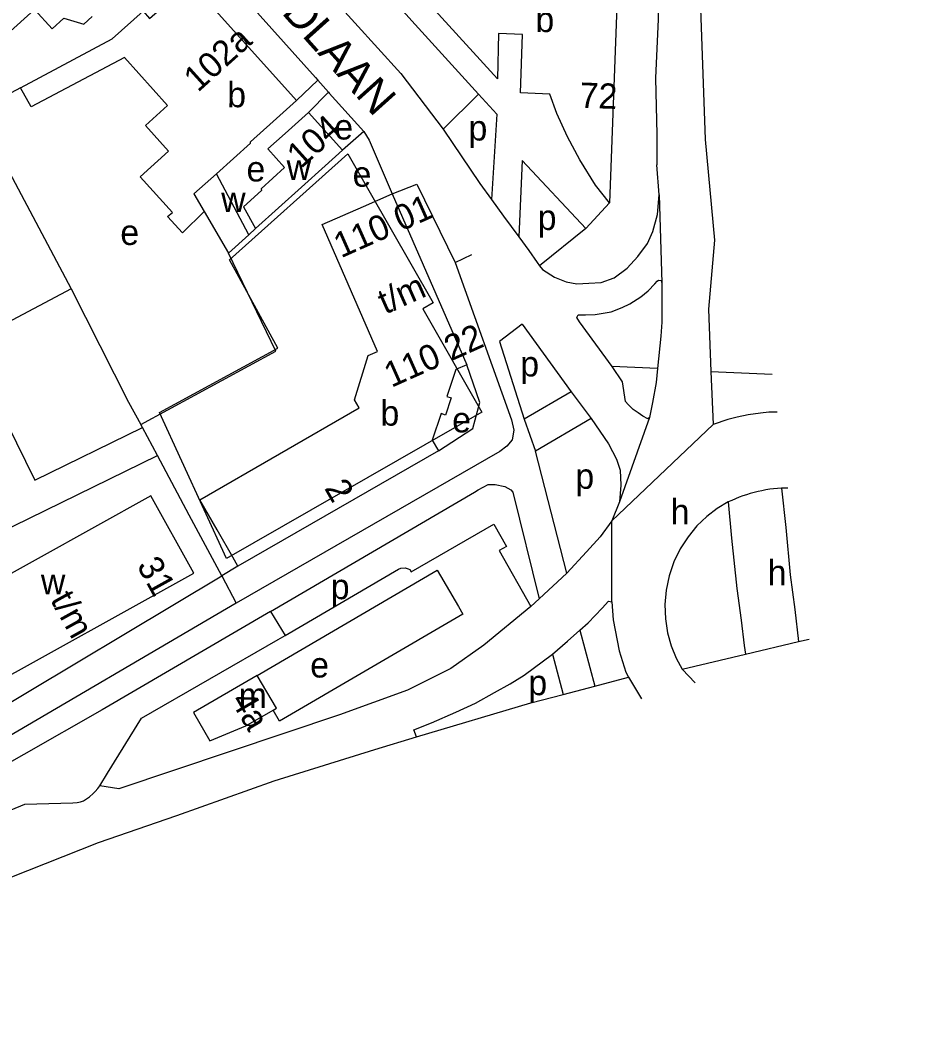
# Model space of a CAD drawing. Extents: x 158356 to 159894, y 383831 to 385260.
# Drawn here: x 159143.9 to 159285.1, y 383926.7 to 384085.1 of the extents above; entities that cross this region are included whole.
import ezdxf

# ---------------------------------------------------------------- set-up
doc = ezdxf.new("R2010")
doc.units = 0
for name, color, linetype in [('BLT_Basislijn', 7, 'Continuous'), ('BLT_Bebouwing', 7, 'Continuous'), ('BLT_Centroide', 7, 'Continuous'), ('BLT_Huisnummer', 7, 'Continuous'), ('BLT_Huisnummer_reeks', 7, 'Continuous'), ('BLT_Onderverdeling_panden', 7, 'Continuous'), ('BLT_Plantopo', 7, 'Continuous'), ('BLT_Straatnaam', 7, 'Continuous'), ('BLT_Vlakafsluiter', 7, 'Continuous')]:
    doc.layers.add(name, color=color, linetype=linetype)

msp = doc.modelspace()

# ---------------------------------------------------------------- linework, layer by layer
at = {"layer": 'BLT_Basislijn'}
for p, q in [((159199.69, 384091.99), (159206.51, 384084.38)), ((159192.14, 384089.95), (159204.25, 384076.61)), ((159216.57, 384073.35), (159206.51, 384084.38)), ((159204.25, 384076.61), (159210.95, 384067.81)), ((159187.7, 384072.36), (159191.11, 384075.54)), ((159191.11, 384075.54), (159192.79, 384073.64)), ((159189.62, 384070.45), (159192.79, 384073.64)), ((159216.57, 384073.35), (159210.95, 384067.81)), ((159216.57, 384073.35), (159219.47, 384070.16)), ((159219.47, 384070.16), (159218.6, 384056.68)), ((159198.4, 384067.44), (159195.01, 384064.47)), ((159223.46, 384062.84), (159222.93, 384050.73)), ((159223.46, 384062.84), (159233.57, 384052.05)), ((159181.22, 384052.05), (159180.14, 384051.05)), ((159233.57, 384052.05), (159226.21, 384046.16)), ((159223.46, 384036.93), (159219.88, 384034.18)), ((159219.88, 384034.18), (159223.81, 384021.85)), ((159244.93, 384029.9), (159237.71, 384030.19)), ((159253.37, 384029.43), (159263.07, 384028.97)), ((159231.24, 384026.17), (159223.81, 384021.85)), ((159231.24, 384026.17), (159234.38, 384021.97)), ((159163.28, 384020.54), (159163.03, 384021.01)), ((159223.81, 384021.85), (159225.6, 384016.76)), ((159234.38, 384021.97), (159225.6, 384016.76)), ((159165.67, 384016.08), (159163.28, 384020.54)), ((159122.87, 383995.19), (159165.67, 384016.08)), ((159230.54, 383997.45), (159225.6, 384016.76)), ((159178.42, 383998.58), (159175.88, 383997.05)), ((159175.88, 383997.05), (159178.17, 383992.69)), ((159181.48, 383981.26), (159209.99, 383997.95)), ((159209.99, 383997.95), (159213.37, 383992.16)), ((159183.57, 383991.39), (159185.91, 383987.57)), ((159214.05, 383990.98), (159185.03, 383974.01)), ((159213.37, 383992.16), (159214.05, 383990.98)), ((159232.63, 383988.41), (159234.96, 383979.56)), ((159258.87, 383984.61), (159267.28, 383986.61)), ((159267.28, 383986.61), (159268.97, 383987.01)), ((159228.29, 383984.6), (159229.96, 383978.25)), ((159248.82, 383982.23), (159258.87, 383984.61)), ((159185.03, 383974.01), (159184.01, 383975.77))]:
    msp.add_line(p, q, dxfattribs=at)
for points in [[(159281.76, 384205.96), (159281.76, 384205.96), (159276.27, 384198.65), (159273.07, 384193.62), (159268.51, 384186.31), (159265.31, 384179.22), (159262.11, 384172.13), (159258.23, 384163.68), (159256.66, 384157.61), (159252.55, 384146.41), (159250.26, 384136.36), (159249.12, 384127.9), (159248.21, 384122.19), (159245.24, 384093.84), (159245.03, 384085.25), (159244.57, 384075.88), (159244.8, 384066.97), (159244.8, 384062.17)], [(159285.08, 384202.55), (159279.24, 384194.76), (159277.53, 384191.59), (159273.88, 384185.74), (159268.77, 384176.24), (159264.87, 384166.99), (159261.47, 384157.49), (159258.06, 384147.25), (159255.87, 384137.51), (159253.92, 384128.74), (159252.46, 384119.48), (159251.97, 384109.01), (159251.48, 384094.39), (159252.46, 384066.14), (159253.94, 384050.22), (159252.97, 384039.26), (159253.37, 384029.43)], [(159150.1, 384121.32), (159190.71, 384075.98), (159191.11, 384075.54)], [(159192.79, 384073.64), (159192.9, 384073.52), (159198.4, 384067.44)], [(159198.4, 384067.44), (159199.22, 384066.08), (159202.88, 384057.53)], [(159210.95, 384067.81), (159216.77, 384059.21), (159218.6, 384056.68)], [(159245.15, 384057.4), (159244.8, 384062.17)], [(159130.07, 384059.7), (159124.27, 384056.8), (159146.23, 384012.21), (159163.28, 384020.54)], [(159202.88, 384057.53), (159206.77, 384059.06), (159212.87, 384046.65)], [(159226.21, 384046.16), (159226.67, 384045.56), (159228.61, 384044.36), (159230.42, 384043.63), (159232.11, 384043.27), (159234.04, 384043.39), (159235.97, 384043.51), (159238.02, 384044.23), (159240.08, 384045.8), (159241.77, 384047.62), (159243.34, 384049.67), (159244.18, 384051.6), (159244.91, 384054.26), (159245.15, 384057.4)], [(159218.6, 384056.68), (159220.52, 384054.02), (159222.93, 384050.73)], [(159237.3, 384056.11), (159233.57, 384052.05)], [(159222.93, 384050.73), (159224.5, 384048.58), (159225.83, 384046.65), (159226.21, 384046.16)], [(159163.03, 384021.01), (159184.45, 384032.63), (159176.91, 384048.14)], [(159212.87, 384046.65), (159215.48, 384047.95)], [(159212.87, 384046.65), (159221.79, 384021.74), (159222.12, 384020.1), (159221.9, 384018.58), (159221.03, 384017.6), (159219.94, 384016.73), (159178.17, 383992.69)], [(159232.12, 384037.94), (159232.32, 384038.39), (159233.51, 384038.39), (159235.02, 384038.44), (159237.58, 384038.86), (159239.29, 384039.53), (159240.53, 384040.1), (159242.28, 384041.24), (159243.42, 384042.19), (159244.51, 384043.28), (159244.84, 384043.7), (159245.08, 384043.89), (159245.51, 384043.8), (159245.6, 384043.47)], [(159245.6, 384043.47), (159245.6, 384040.29), (159245.6, 384037.2), (159245.46, 384035.02), (159244.93, 384029.9)], [(159152.02, 384042.49), (159161.11, 384024.56), (159163.03, 384021.01)], [(159223.46, 384036.93), (159231.24, 384026.17)], [(159237.71, 384030.19), (159232.56, 384037.25), (159232.12, 384037.94)], [(159210.19, 384016.86), (159215.67, 384020.37), (159216.74, 384024.48), (159214.68, 384030.46)], [(159243.66, 384022.11), (159243.37, 384021.92), (159242.61, 384022.35), (159241.85, 384022.87), (159241.05, 384023.39), (159240.29, 384024.15), (159239.86, 384024.63), (159239.39, 384027.76), (159237.71, 384030.19)], [(159244.93, 384029.9), (159244.7, 384027.66), (159244.13, 384024.49), (159243.66, 384022.11)], [(159253.37, 384029.43), (159253.72, 384021.01)], [(159263.87, 384022.98), (159262.54, 384022.95), (159261.24, 384022.8), (159259.27, 384022.54), (159257.56, 384022.16), (159256.05, 384021.8), (159253.72, 384021.01)], [(159263.87, 384022.98), (159263.87, 384022.98)], [(159234.38, 384021.97), (159237.14, 384017.92), (159238.44, 384015.53), (159238.99, 384013.79), (159239.1, 384011.39), (159238.88, 384008.78)], [(159175.88, 383997.05), (159170.71, 384006.63), (159165.67, 384016.08)], [(159216.49, 384010.65), (159218.09, 384011.5), (159219.18, 384011.5), (159220.7, 384011.17), (159221.68, 384010.63), (159222.01, 384010.3), (159226.18, 383993.41)], [(159183.57, 383991.39), (159215.91, 384010.3), (159216.49, 384010.65)], [(159264.55, 384010.93), (159263.93, 384010.89), (159263.31, 384010.82), (159262.69, 384010.74), (159262.07, 384010.64), (159261.45, 384010.52), (159260.84, 384010.39), (159260.23, 384010.24), (159259.62, 384010.07), (159259.02, 384009.89), (159258.42, 384009.69), (159257.83, 384009.47), (159257.25, 384009.24), (159256.68, 384008.99), (159256.11, 384008.73)], [(159265.58, 384010.91), (159265.23, 384010.93), (159264.55, 384010.93)], [(159264.55, 384010.93), (159265.24, 384004.67), (159265.95, 383997.17), (159266.67, 383991.72), (159267.28, 383986.61)], [(159238.88, 384008.78), (159237.68, 384005.73)], [(159256.11, 384008.73), (159254.39, 384007.69), (159252.73, 384006.43), (159251.17, 384004.94), (159249.75, 384003.23), (159248.52, 384001.32), (159247.51, 383999.25), (159246.75, 383997.05), (159246.28, 383994.77), (159246.08, 383992.48), (159246.16, 383990.21), (159246.51, 383988.01), (159247.09, 383985.93), (159247.87, 383983.99), (159248.82, 383982.23)], [(159256.11, 384008.73), (159256.66, 384002.98), (159257.47, 383995.02), (159258.18, 383990.02), (159258.63, 383986), (159258.87, 383984.61)], [(159203.88, 383998.11), (159204.25, 383998.23), (159204.91, 383998.31), (159205.42, 383998.14), (159205.67, 383998.06), (159205.89, 383997.68), (159219, 384005.2), (159220.96, 384001.68), (159219.82, 384001.04), (159224.83, 383992.17)], [(159237.68, 384005.73), (159235.83, 384003.22), (159233.65, 384000.83), (159230.54, 383997.45)], [(159132.98, 383974.65), (159137.54, 383974.11), (159175.88, 383997.05)], [(159185.91, 383987.57), (159203.88, 383998.11)], [(159230.54, 383997.45), (159226.18, 383993.41)], [(159178.17, 383992.69), (159137.39, 383968.84), (159136.17, 383968.1)], [(159224.83, 383992.17), (159226.18, 383993.41)], [(159232.63, 383988.41), (159233.95, 383989.59), (159236.17, 383991.89), (159237.17, 383993.03), (159237.67, 383992.89)], [(159237.67, 383992.89), (159237.91, 383990.08), (159238.82, 383985.15), (159239.89, 383981.78), (159240.3, 383980.96)], [(159183.57, 383991.39), (159156.91, 383975.82), (159119.63, 383954.56), (159067.69, 383929.66)], [(159224.83, 383992.17), (159217.41, 383986.05), (159212.15, 383982.36), (159205.31, 383978.94), (159194.53, 383975), (159159.57, 383963.29), (159156.54, 383963.75)], [(159156.54, 383963.75), (159157.76, 383965.78), (159163.15, 383974.46), (159184.81, 383986.93), (159185.91, 383987.57)], [(159228.29, 383984.6), (159230.66, 383986.66), (159232.63, 383988.41)], [(159206.72, 383971.51), (159206.31, 383972.61), (159209.11, 383973.76), (159212.97, 383975.41), (159216.05, 383976.84), (159219.06, 383978.56), (159221.56, 383979.92), (159223.78, 383981.28), (159228.29, 383984.6)], [(159234.96, 383979.56), (159240.3, 383980.96)], [(159206.72, 383971.51), (159224.84, 383976.91), (159229.96, 383978.25)], [(159229.96, 383978.25), (159234.96, 383979.56)], [(159088.93, 383926.66), (159102.6, 383932.65), (159121.62, 383940.74), (159139.46, 383948.12), (159156.35, 383954.78), (159168.72, 383959.06), (159184.17, 383964.54), (159200.11, 383969.53), (159206.72, 383971.51)], [(159152.29, 383961.04), (159152.96, 383961.1), (159153.49, 383961.21), (159153.95, 383961.37), (159154.44, 383961.69), (159154.88, 383962.04), (159155.51, 383962.54), (159155.82, 383962.86), (159156.25, 383963.33), (159156.54, 383963.75)], [(159081.85, 383931.35), (159109.84, 383943.2), (159117.99, 383946.75), (159125.88, 383953.07), (159144.67, 383960.83), (159152.29, 383961.04)]]:
    msp.add_lwpolyline(points, dxfattribs=at)
at = {"layer": 'BLT_Bebouwing'}
for p, q in [((159170.89, 384091.03), (159187.7, 384072.36)), ((159143.99, 384074.36), (159139.58, 384072.02)), ((159195.01, 384064.47), (159189.62, 384070.45)), ((159140.09, 384064.94), (159152.02, 384042.49)), ((159180.14, 384051.05), (159175.03, 384060.7)), ((159202.88, 384057.53), (159214.68, 384030.46)), ((159173.08, 384054.74), (159176.91, 384048.14)), ((159176.91, 384048.14), (159180.14, 384051.05)), ((159181.48, 383981.26), (159171.39, 383975.38))]:
    msp.add_line(p, q, dxfattribs=at)
for points in [[(159239.94, 384109.7), (159239.35, 384092.98), (159238.7, 384093), (159237.3, 384056.11)], [(159227.86, 384073.32), (159223.22, 384073.57), (159223.51, 384082.82), (159219.74, 384082.98), (159219.55, 384075.78), (159199.19, 384098.16)], [(159135.19, 384076.87), (159146.19, 384086.78), (159149, 384083.71), (159150.86, 384085.39), (159154.01, 384084.46), (159155.32, 384085.64)], [(159168.04, 384054.62), (159162.95, 384060.27), (159167.43, 384064.31), (159163.76, 384068.38), (159167.29, 384071.56), (159160.47, 384079.13), (159145.64, 384071.35), (159143.99, 384074.36)], [(159237.3, 384056.11), (159235.08, 384058.94), (159232.6, 384062.92), (159230.65, 384066.6), (159228.98, 384070.29), (159227.86, 384073.32)], [(159175.03, 384060.7), (159180.44, 384065.57), (159180.4, 384065.78), (159183.99, 384069.01), (159187.7, 384072.36)], [(159189.62, 384070.45), (159185.9, 384067.11), (159183.18, 384064.66), (159185.83, 384061.72), (159182.11, 384058.37), (159182.17, 384058.09), (159179.32, 384055.52), (159181.22, 384052.05)], [(159181.22, 384052.05), (159188.49, 384058.61), (159192.27, 384062)], [(159152.02, 384042.49), (159140.94, 384036.66), (159137.71, 384042.74), (159140.84, 384044.23), (159137.16, 384051.97), (159134.68, 384050.7), (159130.07, 384059.7)], [(159178.42, 383998.58), (159177.6, 384000), (159175.11, 384004.33), (159172.37, 384009.09), (159197.63, 384023.63), (159196.91, 384024.89), (159199.09, 384031.94), (159200.52, 384032.57), (159191.75, 384052.67), (159198.3, 384055.53), (159202.88, 384057.53)], [(159173.08, 384054.74), (159169.62, 384051.35), (159167.28, 384053.94), (159168.04, 384054.62)], [(159214.68, 384030.46), (159212.94, 384029.7), (159211.52, 384025.45), (159212.21, 384025.22), (159211.3, 384022.5), (159210.62, 384022.73), (159209.22, 384018.54), (159210.19, 384016.86)], [(159210.19, 384016.86), (159180.9, 384000), (159178.42, 383998.58)], [(159137.34, 383978.53), (159171.42, 383997.44), (159164.61, 384009.71), (159137.81, 383994.83), (159136.03, 383998.02), (159128.76, 383993.98), (159137.34, 383978.53)], [(159184.01, 383975.77), (159184.52, 383976.06), (159181.48, 383981.26)], [(159171.39, 383975.38), (159173.99, 383970.91), (159179.67, 383973.24), (159184.01, 383975.77)]]:
    msp.add_lwpolyline(points, dxfattribs=at)
at = {"layer": 'BLT_Onderverdeling_panden'}
for p, q in [((159143.99, 384074.36), (159158.52, 384082.1)), ((159195.01, 384064.47), (159192.27, 384062)), ((159175.03, 384060.7), (159171.43, 384057.57)), ((159171.43, 384057.57), (159173.08, 384054.74))]:
    msp.add_line(p, q, dxfattribs=at)
msp.add_lwpolyline([(159158.52, 384082.1), (159163.43, 384086.47), (159164.43, 384085.34), (159170.89, 384091.03)], dxfattribs=at)
at = {"layer": 'BLT_Plantopo'}
msp.add_lwpolyline([(159166, 384022.9), (159184.75, 384033.09), (159177.11, 384047.12), (159195.82, 384063.88), (159209.36, 384040.28), (159207.71, 384039.33), (159217.06, 384022.97), (159176.6, 383999.8)], close=True, dxfattribs=at)
at = {"layer": 'BLT_Vlakafsluiter'}
for p, q in [((159245.15, 384057.4), (159245.6, 384043.47)), ((159237.68, 384005.73), (159253.72, 384021.01)), ((159243.66, 384022.11), (159238.88, 384008.78)), ((159237.67, 383992.89), (159237.68, 384005.73)), ((159248.82, 383982.23), (159250.87, 383980.07)), ((159240.3, 383980.96), (159242.37, 383977.54))]:
    msp.add_line(p, q, dxfattribs=at)

# ---------------------------------------------------------------- texts
at = {"layer": 'BLT_Centroide'}
for s, p in [('b', (159225.57, 384083.19)), ('b', (159176.73, 384071.28)), ('e', (159193.7, 384066.16)), ('p', (159214.97, 384066)), ('e', (159179.79, 384059.51)), ('w', (159186.15, 384059.77)), ('e', (159196.6, 384058.68)), ('w', (159175.78, 384054.67)), ('p', (159225.93, 384051.83)), ('e', (159159.79, 384049.45)), ('p', (159223.17, 384028.62)), ('b', (159201.02, 384020.83)), ('e', (159212.38, 384019.76)), ('p', (159231.9, 384010.82)), ('h', (159247, 384005.19)), ('h', (159262.37, 383995.54)), ('w', (159147.21, 383994.12)), ('p', (159193.14, 383993.33)), ('e', (159189.88, 383980.92)), ('p', (159224.45, 383978.12)), ('m', (159178.55, 383976.09))]:
    msp.add_text(s, height=4, dxfattribs=at).set_placement(p)
at = {"layer": 'BLT_Huisnummer'}
for s, rotation, p in [('102a', 42.0279, (159172.08, 384073.54)), ('104', 42.0065, (159188.43, 384061.46)), ('110 01', 24.0065, (159194.75, 384047.32)), ('t/m', 24.0065, (159201.76, 384038.4)), ('110 22', 24.0065, (159202.74, 384026.8)), ('4a', 300.2437, (159177.18, 383977.29))]:
    msp.add_text(s, height=4, rotation=rotation, dxfattribs=at).set_placement(p)
at = {"layer": 'BLT_Huisnummer_reeks'}
for s, rotation, p in [('72', 357.9046, (159232.52, 384071.21)), ('2', 299.9282, (159192.04, 384010.92)), ('31', 299.036, (159162.32, 383998.66)), ('t/m', 299.036, (159148.62, 383993.26))]:
    msp.add_text(s, height=4, rotation=rotation, dxfattribs=at).set_placement(p)
at = {"layer": 'BLT_Straatnaam'}
msp.add_text('KOENRAADLAAN', height=5, rotation=311.8995, dxfattribs=at).set_placement((159163.4, 384110.53))

doc.saveas('drawing.dxf')
